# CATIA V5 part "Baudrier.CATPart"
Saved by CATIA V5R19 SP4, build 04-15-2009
Part number: Baudrier
Bounding box of the stored display mesh (mm): x -514.957 to -264.957, y 410.141 to 513.171, z 0 to 500
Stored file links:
  G:\EU_thinkMotion\CFAO_2010\MMS_groupe1\MMS_groupe1\OK\rragonneau\rragonneau\Baudrier.CATPart
  F:\Squelette\Deambulateur.CATProduct
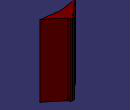
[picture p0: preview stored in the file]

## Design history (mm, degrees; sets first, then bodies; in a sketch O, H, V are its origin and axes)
External parameters (linked from other documents)
  `External.diam_moyeu_ext / epaisseur_bras&montant` = 60 mm
  External.largeur_siege = 500 mm
Set1
  Sketch1 on xy-plane, origin (0, 0, 0), H (1, 0, 0), V (0, 1, 0)
    line L1 (-514.9567, 410.1408) -> (-404.9567, 498.1706)
    point P1 (-514.9567, 410.1408)
    point P2 (-404.9567, 498.1706)
    point P3 (-389.9567, 498.1706)
    line L2 (-514.9567, 410.1408) -> (-389.9567, 427.7084)
    point P4 (-389.9567, 427.7084)
    axis line L3 (-389.9567, 546.7676) -> (-389.9567, 326.3221)
    point P7 (-389.9567, 498.1706)
    point P8 (-374.9567, 498.1706)
    point P9 (-374.9567, 498.1706)
    point P10 (-264.9567, 410.1408)
    line L4 (-264.9567, 410.1408) -> (-374.9567, 498.1706)
    point P11 (-389.9567, 427.7084)
    point P12 (-264.9567, 410.1408)
    line L5 (-264.9567, 410.1408) -> (-389.9567, 427.7084)
    line L6 (-404.9567, 498.1706) -> (-404.9567, 513.1706)
    point P13 (-404.9567, 498.1706)
    point P14 (-404.9567, 513.1706)
    line L7 (-389.9567, 513.1706) -> (-404.9567, 513.1706)
    point P15 (-389.9567, 513.1706)
    point P16 (-374.9567, 513.1706)
    point P17 (-374.9567, 498.1706)
    line L8 (-374.9567, 498.1706) -> (-374.9567, 513.1706)
    point P18 (-374.9567, 513.1706)
    point P19 (-389.9567, 513.1706)
    line L9 (-389.9567, 513.1706) -> (-374.9567, 513.1706)
    angle L3 L2 = 82
    distance L3 P1 = 125 {= External.largeur_siege /4}
    length L7 = 15 {= `External.diam_moyeu_ext / epaisseur_bras&montant` /4}
    length L6 = 15 {= `External.diam_moyeu_ext / epaisseur_bras&montant` /4}
    vertical: L3 V, L6 V
    coincidence: P3 L3, P4 L3, P3 P7, P4 P11, P8 P9, P10 P12, P15 L3, P2 P13
    symmetry: P3 P7 L3, P2 P8 L3, P2 P9 L3, P1 P10 L3, L1 L4 L3, P4 P11 L3, P1 P12 L3, L2 L5 L3, P14 P16 L3, P13 P17 L3, L6 L8 L3, P14 P18 L3, P15 P19 L3, L7 L9 L3
    horizontal: L7 H
Body1 (main body)
  Pad1: profile Sketch1, direction (0, 0, 1), length 500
